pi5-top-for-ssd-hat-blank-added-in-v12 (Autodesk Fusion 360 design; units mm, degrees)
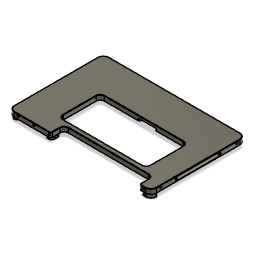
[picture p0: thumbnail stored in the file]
base_feature "Base Feature"
fillet "Fillet1" radius 0.2
sketch "Sketch1" plane through (0, 2.1205, 0) normal (0, 1, 0) x axis (-1, 0, 0)
  line L1 (-84.4, 19.9658) -> (-81.7, 19.9658)
  line L2 (-87.5, -33.95) -> (-87.5, 16.8658)
  line L3 (-4.6, -37.25) -> (-84.2, -37.25)
  line L4 (-1.3, 16.6658) -> (-1.3, -33.95)
  line L5 (-25.7003, 19.9658) -> (-4.6, 19.9658)
  line L6 (-26.5003, 14.5068) -> (-26.5003, 19.1658)
  line L7 (-78.2083, 11.9581) -> (-29.2086, 11.8068)
  line L8 (-80.9, 19.1658) -> (-80.9, 14.6581)
  line L9 (-23.4134, 9.4509) -> (-71.4134, 9.4509)
  line L10 (-20.7134, -13.2491) -> (-20.7134, 6.7509)
  line L11 (-71.4134, -15.9491) -> (-23.4134, -15.9491)
  line L12 (-74.1134, 6.7509) -> (-74.1134, -13.2491)
  line L13 (-1.3, -33.95) -> (-1.3, -39.7872)
  line L14 (-4.2, -39.7872) -> (-1.3, -39.7872)
  line L15 (-4.2, 24) -> (-4.2, -39.7872)
  line L16 (-1.3, 24) -> (-4.2, 24)
  line L17 (-1.3, -39.7872) -> (-1.3, 24)
  line L18 (-87.8104, 19.9658) -> (-81.7, 19.9658)
  line L19 (-87.8104, 15.3658) -> (-87.8104, 19.9658)
  line L20 (-81.7, 15.3658) -> (-87.8104, 15.3658)
  line L21 (-81.7, 19.9658) -> (-81.7, 15.3658)
  arc A1 centre (-81.7, 19.1658) radius 0.8 clockwise from (-81.7, 19.9658) to (-80.9, 19.1658)
  arc A2 centre (-84.4, 16.8658) radius 3.1 clockwise from (-87.5, 16.8658) to (-84.4, 19.9658)
  arc A3 centre (-84.2, -33.95) radius 3.3 clockwise from (-84.2, -37.25) to (-87.5, -33.95)
  arc A4 centre (-4.6, -33.95) radius 3.3 clockwise from (-1.3, -33.95) to (-4.6, -37.25)
  arc A5 centre (-4.6, 16.6658) radius 3.3 clockwise from (-4.6, 19.9658) to (-1.3, 16.6658)
  arc A6 centre (-25.7003, 19.1658) radius 0.8 clockwise from (-26.5003, 19.1658) to (-25.7003, 19.9658)
  arc A7 centre (-29.2003, 14.5068) radius 2.7 clockwise from (-26.5003, 14.5068) to (-29.2086, 11.8068)
  arc A8 centre (-78.2, 14.6581) radius 2.7 clockwise from (-78.2083, 11.9581) to (-80.9, 14.6581)
  arc A9 centre (-23.4134, 6.7509) radius 2.7 clockwise from (-23.4134, 9.4509) to (-20.7134, 6.7509)
  arc A10 centre (-23.4134, -13.2491) radius 2.7 clockwise from (-20.7134, -13.2491) to (-23.4134, -15.9491)
  arc A11 centre (-71.4134, -13.2491) radius 2.7 clockwise from (-71.4134, -15.9491) to (-74.1134, -13.2491)
  arc A12 centre (-71.4134, 6.7509) radius 2.7 clockwise from (-74.1134, 6.7509) to (-71.4134, 9.4509)
  point P12 (-1.3, -33.95)
  point P38 (-1.3, -33.95)
  point P3 (-81.7, 19.9658)
  point P43 (-81.7, 19.9658)
  point P39 (-1.3, -39.7872)
  point P40 (-4.2, -39.7872)
  point P46 (-81.7, 15.3658)
  vertical L13
  coincident P12 P38
  horizontal L14
  vertical L15
  horizontal L16
  vertical L17
  horizontal L18
  vertical L19
  horizontal L20
  vertical L21
  coincident P3 P43
  dimension "d21" distance P39 P40 = 2.9
  dimension "d23" distance P43 P46 = 4.6
extrude "Extrude1" add sketch "Sketch1" profile of L1 A2 L2 L18 L20 L21 against normal blind 5
extrude "Extrude2" add sketch "Sketch1" profile of A4 L4 A5 L15 L17 against normal blind 5.5 (magnitude of "-2.85 mm - 2.65 mm")
fillet "Fillet2" radius 1.5
extrude "Extrude3" add sketch "Sketch1" profile of A4 L4 A5 L15 L17 against normal blind 5.5
fillet "Fillet3" radius 1.4
sketch "Sketch2" plane through (0, -0.7295, 0) normal (0, -1, 0) x axis (1, 0, 0)
  line L1 (1.3, 16.6658) -> (1.3, -33.95)
  line L2 (4.2, -34.5582) -> (4.2, 17.2741)
  line L3 (46, -24) -> (53.0859, -24)
  line L4 (45, -16.7491) -> (45, -23)
  line L5 (23.4134, -15.7491) -> (44, -15.7491)
  line L6 (20.9134, 6.7509) -> (20.9134, -13.2491)
  line L7 (71.4134, 9.2509) -> (23.4134, 9.2509)
  line L8 (73.9134, 2) -> (73.9134, 6.7509)
  line L9 (81, 1) -> (74.9134, 1)
  line L10 (82, -11.8932) -> (82, 0)
  line L11 (74.8537, -12.8932) -> (81, -12.8932)
  line L12 (55.0859, -15.7491) -> (71.4134, -15.7491)
  line L13 (54.0859, -23) -> (54.0859, -16.7491)
  line L14 (80.7, 14.6581) -> (80.7, 19.1658)
  line L15 (29.208, 12.0068) -> (78.2077, 12.1581)
  line L16 (26.7003, 19.1658) -> (26.7003, 14.5068)
  line L17 (4.6, 20.1658) -> (25.7003, 20.1658)
  line L18 (1.1, -33.95) -> (1.1, 16.6658)
  line L19 (84.2, -37.45) -> (4.6, -37.45)
  line L20 (87.7, 16.8658) -> (87.7, -33.95)
  line L21 (81.7, 20.1658) -> (84.4, 20.1658)
  line L22 (84.4, 19.9658) -> (83.2, 19.9658)
  line L23 (83.2, 15.3658) -> (86, 15.3658)
  line L24 (81.7, 18.4658) -> (81.7, 16.8658)
  line L25 (22.0173, 13.3579) -> (23.6224, 13.3579)
  line L26 (22.0173, 16.8579) -> (22.0173, 13.3579)
  line L27 (26.108, 13.3579) -> (22.0173, 13.3579)
  line L28 (26.108, 19.0973) -> (26.108, 13.3579)
  line L29 (22.0173, 19.0973) -> (26.108, 19.0973)
  line L30 (22.0173, 13.3579) -> (22.0173, 19.0973)
  arc A1 centre (4.6, 16.6658) radius 3.3 clockwise from (1.3, 16.6658) to (1.4737, 17.7223)
  arc A2 centre (2.8, 17.2741) radius 1.4 clockwise from (1.4737, 17.7223) to (4.2, 17.2741)
  arc A3 centre (2.8, -34.5582) radius 1.4 clockwise from (4.2, -34.5582) to (1.4737, -35.0064)
  arc A4 centre (4.6, -33.95) radius 3.3 clockwise from (1.4737, -35.0064) to (1.3, -33.95)
  arc A5 centre (53.0859, -23) radius 1 clockwise from (54.0859, -23) to (53.0859, -24)
  arc A6 centre (46, -23) radius 1 clockwise from (46, -24) to (45, -23)
  arc A7 centre (44, -16.7491) radius 1 clockwise from (44, -15.7491) to (45, -16.7491)
  arc A8 centre (23.4134, -13.2491) radius 2.5 clockwise from (23.4134, -15.7491) to (20.9134, -13.2491)
  arc A9 centre (23.4134, 6.7509) radius 2.5 clockwise from (20.9134, 6.7509) to (23.4134, 9.2509)
  arc A10 centre (71.4134, 6.7509) radius 2.5 clockwise from (71.4134, 9.2509) to (73.9134, 6.7509)
  arc A11 centre (74.9134, 2) radius 1 clockwise from (74.9134, 1) to (73.9134, 2)
  arc A12 centre (81, 0) radius 1 clockwise from (81, 1) to (82, 0)
  arc A13 centre (81, -11.8932) radius 1 clockwise from (82, -11.8932) to (81, -12.8932)
  arc A14 centre (74.8537, -13.8932) radius 1 clockwise from (73.8708, -13.7092) to (74.8537, -12.8932)
  arc A15 centre (71.4134, -13.2491) radius 2.5 clockwise from (73.8708, -13.7092) to (71.4134, -15.7491)
  arc A16 centre (55.0859, -16.7491) radius 1 clockwise from (54.0859, -16.7491) to (55.0859, -15.7491)
  arc A17 centre (81.7, 19.1658) radius 1 clockwise from (80.7, 19.1658) to (81.7, 20.1658)
  arc A18 centre (78.2, 14.6581) radius 2.5 clockwise from (80.7, 14.6581) to (78.2077, 12.1581)
  arc A19 centre (29.2003, 14.5068) radius 2.5 clockwise from (29.208, 12.0068) to (26.7003, 14.5068)
  arc A20 centre (25.7003, 19.1658) radius 1 clockwise from (25.7003, 20.1658) to (26.7003, 19.1658)
  arc A21 centre (4.6, 16.6658) radius 3.5 clockwise from (1.1, 16.6658) to (4.6, 20.1658)
  arc A22 centre (4.6, -33.95) radius 3.5 clockwise from (4.6, -37.45) to (1.1, -33.95)
  arc A23 centre (84.2, -33.95) radius 3.5 clockwise from (87.7, -33.95) to (84.2, -37.45)
  arc A24 centre (84.4, 16.8658) radius 3.3 clockwise from (84.4, 20.1658) to (87.7, 16.8658)
  arc A25 centre (84.4, 16.8658) radius 3.1 clockwise from (84.4, 19.9658) to (87.5, 16.8658)
  arc A26 centre (86, 16.8658) radius 1.5 clockwise from (87.5, 16.8658) to (86, 15.3658)
  arc A27 centre (83.2, 16.8658) radius 1.5 clockwise from (83.2, 15.3658) to (81.7, 16.8658)
  arc A28 centre (83.2, 18.4658) radius 1.5 clockwise from (81.7, 18.4658) to (83.2, 19.9658)
  circle C1 centre (83.1747, -32.5254) radius 2.5
  circle C2 centre (25.1235, -32.5254) radius 2.5
  horizontal L25
  vertical L26
  horizontal L27
  vertical L28
  horizontal L29
  vertical L30
extrude "Extrude4" add sketch "Sketch2" profile of L25 L26 L27 L28 L29 L30 along normal blind 2.15
fillet "Fillet4" radius 2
